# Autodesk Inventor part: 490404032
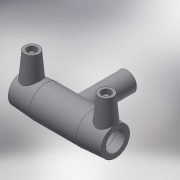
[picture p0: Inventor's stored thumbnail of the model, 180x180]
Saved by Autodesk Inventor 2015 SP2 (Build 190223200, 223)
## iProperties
Created: 2017-06
Part Number: 490404032
Material: Generic
Description: PLASSON TEE 32-32-32
Document SubType Name: Modeling
Designer: KIM
Mass: 57.3761 g
Surface Area: 241.06 cm^2
Volume: 57.3761 cm^3
Density: 1 g/cm^3
Appearance: Default
Author: KIM
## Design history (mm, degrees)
derived "490404.ipt"
feature "Solid1::490404.ipt"
tag "TaggingFeature1"
body "Solid1"
other parameters: "d0" = 104, "d1" = 32, "d2" = 44, "d3" = 39, "d4" = 26, "d5" = 39.6, "d6" = 30.4, "d7" = 32, "d8" = 168 deg, "d10" = 15.6, "d11" = 5.2, "d13" = 104, "d14" = 17.6296, "d17" = 28.8, "d18" = 32, "d19" = 3.52592, "d20" = 168 deg, "d22" = 40.92, "d23" = 44, "d24" = 39.6924, "d25" = 135 deg, "d26" = 72.8, "d27" = 135 deg, "d29" = 43, "d30" = 15, "d31" = 41.6, "d34" = 5 deg, "d35" = 15, "d39" = 5 deg, "d40" = 9.6, "d41" = 4.8, "d42" = 6, "d43" = 0, "d45" = 4, "d46" = 14, "d47" = 0, "d48" = -74, "d49" = 32, "d51" = 0, "d52" = 25.6, "d54" = 0, "d55" = 39.6, "d56" = 44, "d57" = 36.4, "d58" = 135 deg, "d59" = 39, "d60" = 39, "d61" = 135 deg, "d62" = 74, "d72" = 47.32, "d73" = 23.66, "d74" = -74, "d75" = 33.6, "d77" = 0, "d78" = 25.6, "d80" = 0, "d81" = 32, "d82" = 52, "d83" = 0, "d84" = 3, "d85" = 0, "d86" = 3, "d87" = 0, "d88" = 11.31, "d89" = 2.8275, "d90" = 11.31, "d_" = 32, "L_" = 104, "L_1" = 39, "D_" = 44, "A_" = 43, "d_2" = 12, "H_" = 74
